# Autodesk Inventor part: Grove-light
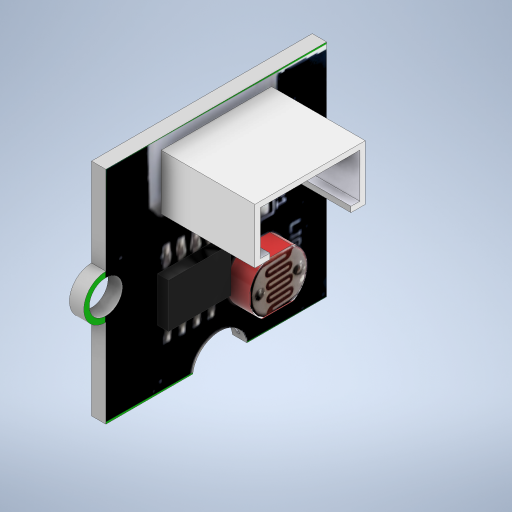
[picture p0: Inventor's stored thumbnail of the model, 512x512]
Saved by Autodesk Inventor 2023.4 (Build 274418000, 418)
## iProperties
Created: 2022-12
Part Number: Grove-light
Material: Générique
Document SubType Name: Modeling
Designer: ecuenot
Density: 1 g/cm^3
Appearance: Par défaut
Author: ecuenot
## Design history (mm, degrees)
sketch "Esquisse1"
  geometry: L1 (20, 0)-(20, -20); L2 (0, -20)-(0, 0); L3 (11.5, 0)-(12, 0); L4 (10, 0)-(8, 0); L5 (0, 0)-(8, 0); L6 (11.5, 0)-(20, 0); L7 (20, -20)-(12, -20); L8 (8, -20)-(0, -20); C1 r 1.5 at (10, -20); A1 r 2 centre (10, 0) between (12, 0) and (8, 0); A2 r 2 centre (10, -20) between (8, -20) and (12, -20); 2 further points
  constraints: 16 end point, 5 parallel, 4 point on circle, 3 centre point, 2 coincident, 2 horizontal, 2 perpendicular, 1 horizontal alignment, 2 other
  dimensions: "d0" = 20 distance of L1.end L2.start; "d1" = 20 distance of L1.start L1.end
extrude "Extrusion1" new body sketch "Esquisse1" distance "d9" = 1.3; taper "d10" = 0 deg
sketch "Esquisse6"
  geometry: L1 (20, 20)-(0, 20) reference; L2 (15, 14)-(5, 14); L3 (5, 14)-(5, 19); L4 (5, 19)-(15, 19); L5 (15, 19)-(15, 14); L6 (15, 14)-(5, 19); L7 (5, 14)-(15, 19); 2 further points
  constraints: 12 end point, 2 midpoint, 2 parallel, 1 horizontal, 1 perpendicular
  dimensions: "d36" = 10 distance of L3.end L4.end; "d37" = 5 distance of L2.end L3.end
extrude "Extrusion4" join sketch "Esquisse6" distance "d38" = 8.5; taper "d39" = 0 deg
feature "Coque2" dims "d41" = 0.5
sketch "Esquisse7"
  geometry: L1 (3.749, 1.295)-(8.801, 1.295); L2 (8.801, 1.295)-(8.801, 8.634); L3 (8.801, 8.634)-(3.749, 8.634); L4 (3.749, 8.634)-(3.749, 1.295); L5 (3.749, 1.295)-(8.801, 8.634); L6 (8.801, 1.295)-(3.749, 8.634); 1 further point
  constraints: 12 end point, 2 parallel, 1 horizontal, 1 perpendicular
extrude "Extrusion5" cut sketch "Esquisse7" stored distance "d44" = 8.5; taper "d45" = 0 deg
sketch "Esquisse8" dims "d52" = 10
  geometry: L1 (-4.5, 7.064)-(-14.5, 7.064) reference; C1 r 0.5 at (-12.533, 4.536); C2 r 0.5 at (-10.533, 4.536); C3 r 0.5 at (-8.533, 4.536); C4 r 0.5 at (-6.533, 4.536); 1 further point
  constraints: 4 centre point, 1 horizontal, 6 other
  dimensions: "d46" = 1 diameter of C1; "d49" = 2 distance of C1.centre C2.centre
extrude "Extrusion6" join sketch "Esquisse8" distance "d54" = 7; taper "d55" = 0 deg
fillet "Congé2" dims "d56" = 0.5
sketch "Esquisse9"
  geometry: L1 (0, 20)-(0, 12) reference; L2 (0, 20)-(20.229, 19.849); L3 (20.229, 19.849)-(20.081, 0); L4 (20.081, 0)-(-0.148, 0.151); L5 (-0.148, 0.151)-(0, 20); 1 further point; 1 other entity
  constraints: 2 other
feature "Décalcomanie3" sketch "Esquisse9"
sketch "Esquisse10"
  geometry: L1 (-20, 20)-(0, 20) reference; L2 (-20, 20)-(-0.046, 20.046); L3 (-0.046, 20.046)-(0, 0); L4 (0, 0)-(-19.954, -0.046); L5 (-19.954, -0.046)-(-20, 20); 1 further point; 1 other entity
  constraints: 1 coincident, 2 other
feature "Décalcomanie4" sketch "Esquisse10"
sketch "Esquisse11"
  geometry: L1 (0, 0)-(20, 0) reference; C1 r 2.474 at (10.322, -0.327); 2 further points
  constraints: 1 centre point
extrude "Extrusion7" cut sketch "Esquisse11" distance "d73" = 7; taper "d74" = 0 deg
sketch "Esquisse12"
  geometry: L1 (10.32, 9.472)-(4.671, 9.472); L2 (4.671, 9.472)-(4.671, 5.431); L3 (4.671, 5.431)-(10.32, 5.431); L4 (10.32, 5.431)-(10.32, 9.472); 1 further point
  constraints: 8 end point, 2 parallel, 1 horizontal, 1 perpendicular
extrude "Extrusion8" join sketch "Esquisse12" distance "d75" = 1; taper "d76" = 0 deg
sketch "Esquisse13"
  geometry: L1 (12.472, 7.664)-(14.82, 7.664); L2 (12.165, 3.18)-(14.977, 3.18); A1 r 2.574 centre (13.571, 5.336) between (12.472, 7.664) and (12.165, 3.18); A2 r 2.541 centre (13.706, 5.38) between (14.977, 3.18) and (14.82, 7.664); 1 further point
  constraints: 6 point on circle, 4 end point, 2 centre point, 1 horizontal
extrude "Extrusion9" join sketch "Esquisse13" distance "d77" = 2; taper "d78" = 0 deg
sketch "Esquisse14"
  geometry: L1 (11.102, 7.627)-(16.229, 7.627); L2 (16.229, 7.627)-(16.229, 3.254); L3 (16.229, 3.254)-(11.102, 3.254); L4 (11.102, 3.254)-(11.102, 7.627); 1 further point; 1 other entity
  constraints: 2 other
feature "Décalcomanie5" sketch "Esquisse14"
node "Solide1"
node "Image5"
node "Image6"
node "Image7"
